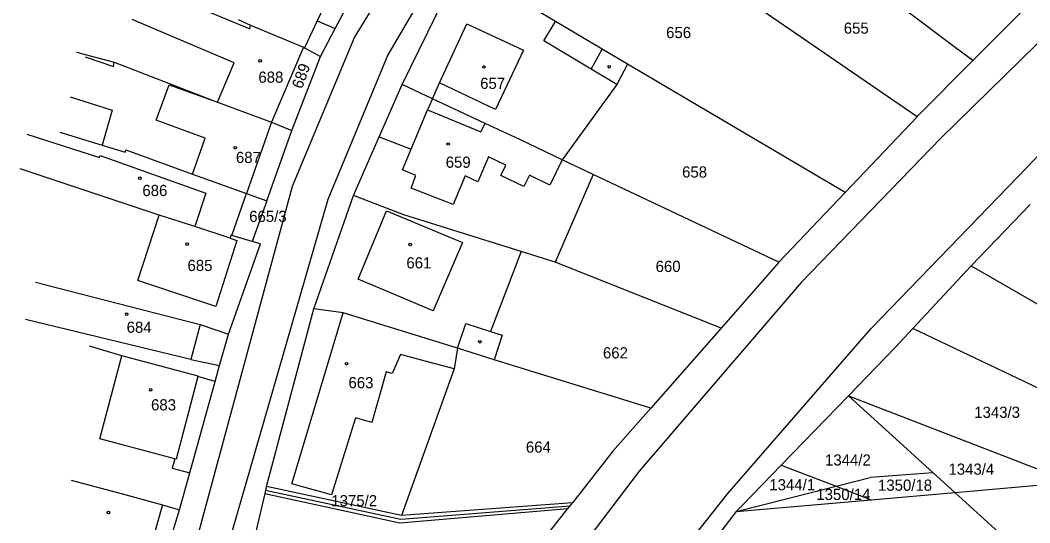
# Model space of a CAD drawing. Extents: x -563148 to -561712, y -1182311 to -1179502.
# Drawn here: x -562823.3 to -562687.9, y -1181313.6 to -1181246.2 of the extents above; entities that cross this region are included whole.
import ezdxf

# ---------------------------------------------------------------- set-up
doc = ezdxf.new("R2010")
doc.units = 0
for name, color, linetype in [('Vrstva 55', 7, 'Continuous'), ('Vrstva 56', 7, 'Continuous'), ('Vrstva 57', 7, 'Continuous')]:
    doc.layers.add(name, color=color, linetype=linetype)

msp = doc.modelspace()

# ---------------------------------------------------------------- linework, layer by layer
at = {"layer": 'Vrstva 55'}
for p, q in [((-562772.07, -1181254.85), (-562764.25, -1181238.82)), ((-562751.51, -1181246.42), (-562764.25, -1181238.82)), ((-562695.59, -1181251.65), (-562682.72, -1181238.72)), ((-562703.06, -1181259.17), (-562728.04, -1181242.02)), ((-562781.04, -1181247.33), (-562779.24, -1181243.92)), ((-562697.78, -1181250.01), (-562704.76, -1181244.75)), ((-562794.05, -1181246.16), (-562792.4, -1181246.88)), ((-562792.4, -1181246.88), (-562785.29, -1181249.87)), ((-562783.04, -1181251.1), (-562781.04, -1181247.33)), ((-562745.28, -1181250.13), (-562751.51, -1181246.42)), ((-562785.29, -1181249.87), (-562789.59, -1181259.92)), ((-562785.29, -1181249.87), (-562785.19, -1181249.96)), ((-562785.19, -1181249.96), (-562783.04, -1181251.1)), ((-562741.87, -1181252.15), (-562745.28, -1181250.13)), ((-562695.59, -1181251.65), (-562697.78, -1181250.01)), ((-562814.57, -1181251.14), (-562810.77, -1181252.43)), ((-562786.85, -1181261.03), (-562783.04, -1181251.1)), ((-562810.77, -1181252.43), (-562810.69, -1181251.87)), ((-562810.69, -1181251.87), (-562796.85, -1181257.21)), ((-562741.87, -1181252.15), (-562743.28, -1181254.87)), ((-562712.67, -1181269.31), (-562741.87, -1181252.15)), ((-562702.89, -1181258.99), (-562695.59, -1181251.65)), ((-562775.14, -1181261.85), (-562772.07, -1181254.85)), ((-562768.02, -1181256.76), (-562772.07, -1181254.85)), ((-562743.28, -1181254.87), (-562750.65, -1181264.94)), ((-562760.93, -1181260.09), (-562768.02, -1181256.76)), ((-562796.85, -1181257.21), (-562789.59, -1181259.92)), ((-562712.67, -1181269.31), (-562703.06, -1181259.17)), ((-562703.06, -1181259.17), (-562702.89, -1181258.99)), ((-562790.23, -1181270.46), (-562786.85, -1181261.03)), ((-562789.59, -1181259.92), (-562786.85, -1181261.03)), ((-562756.3, -1181262.23), (-562760.93, -1181260.09)), ((-562817.95, -1181261.26), (-562812.31, -1181262.99)), ((-562778.6, -1181269.72), (-562775.14, -1181261.85)), ((-562750.65, -1181264.94), (-562756.3, -1181262.23)), ((-562812.31, -1181262.99), (-562809.23, -1181263.94)), ((-562809.23, -1181263.94), (-562809.11, -1181263.61)), ((-562809.11, -1181263.61), (-562800.2, -1181266.89)), ((-562746.48, -1181266.91), (-562750.65, -1181264.94)), ((-562804.67, -1181272.35), (-562823.28, -1181266.16)), ((-562800.2, -1181266.89), (-562792.94, -1181269.48)), ((-562746.48, -1181266.91), (-562751.55, -1181278.69)), ((-562721.58, -1181278.68), (-562746.48, -1181266.91)), ((-562794.91, -1181275.09), (-562792.94, -1181269.48)), ((-562792.94, -1181269.48), (-562790.23, -1181270.46)), ((-562790.23, -1181270.46), (-562792.18, -1181275.9)), ((-562783.92, -1181284.92), (-562778.6, -1181269.72)), ((-562771.87, -1181272.31), (-562778.6, -1181269.72)), ((-562721.58, -1181278.68), (-562712.67, -1181269.31)), ((-562687.87, -1181270.93), (-562695.79, -1181279.15)), ((-562799.86, -1181273.88), (-562804.67, -1181272.35)), ((-562759.56, -1181276.15), (-562771.87, -1181272.31)), ((-562795.13, -1181275.43), (-562799.86, -1181273.88)), ((-562795.05, -1181275.05), (-562795.13, -1181275.43)), ((-562794.91, -1181275.09), (-562795.05, -1181275.05)), ((-562792.18, -1181275.9), (-562794.91, -1181275.09)), ((-562791.06, -1181276.23), (-562792.18, -1181275.9)), ((-562795.37, -1181288.31), (-562791.06, -1181276.23)), ((-562756.11, -1181277.24), (-562760.23, -1181287.98)), ((-562756.11, -1181277.24), (-562759.56, -1181276.15)), ((-562751.55, -1181278.69), (-562756.11, -1181277.24)), ((-562729.32, -1181287.5), (-562751.55, -1181278.69)), ((-562721.8, -1181278.93), (-562729.32, -1181287.5)), ((-562721.58, -1181278.68), (-562721.8, -1181278.93)), ((-562695.79, -1181279.15), (-562703.62, -1181287.57)), ((-562695.79, -1181279.15), (-562654.44, -1181303.1)), ((-562821.24, -1181281.33), (-562799.16, -1181287.04)), ((-562790.26, -1181308.73), (-562783.92, -1181284.92)), ((-562779.97, -1181285.44), (-562783.92, -1181284.92)), ((-562764.66, -1181290.2), (-562779.97, -1181285.44)), ((-562799.16, -1181287.04), (-562795.37, -1181288.31)), ((-562760.23, -1181287.98), (-562758.68, -1181288.47)), ((-562729.32, -1181287.5), (-562738.75, -1181298.24)), ((-562703.62, -1181287.57), (-562705.97, -1181290.09)), ((-562663.74, -1181306.52), (-562703.62, -1181287.57)), ((-562796.55, -1181292.52), (-562795.37, -1181288.31)), ((-562758.68, -1181288.47), (-562759.74, -1181291.78)), ((-562809.66, -1181291.24), (-562814.01, -1181289.91)), ((-562764.66, -1181290.2), (-562765.11, -1181292.98)), ((-562759.74, -1181291.78), (-562764.66, -1181290.2)), ((-562712.25, -1181296.57), (-562705.97, -1181290.09)), ((-562806.12, -1181292.17), (-562809.66, -1181291.24)), ((-562799.43, -1181293.94), (-562806.12, -1181292.17)), ((-562738.75, -1181298.24), (-562759.74, -1181291.78)), ((-562797.16, -1181294.67), (-562796.55, -1181292.52)), ((-562765.11, -1181292.98), (-562772.17, -1181312.61)), ((-562800.55, -1181306.89), (-562797.16, -1181294.67)), ((-562799.45, -1181294.01), (-562799.43, -1181293.94)), ((-562797.16, -1181294.67), (-562799.45, -1181294.01)), ((-562721.28, -1181305.89), (-562712.25, -1181296.57)), ((-562712.25, -1181296.57), (-562682.3, -1181308.15)), ((-562700.89, -1181306.91), (-562712.25, -1181296.57)), ((-562738.75, -1181298.24), (-562743.82, -1181304.01)), ((-562743.82, -1181304.01), (-562749.23, -1181310.92)), ((-562801.94, -1181311.87), (-562800.55, -1181306.89)), ((-562726.43, -1181311.21), (-562721.28, -1181305.89)), ((-562721.28, -1181305.89), (-562713.92, -1181308.71)), ((-562700.89, -1181306.91), (-562709.36, -1181307.55)), ((-562700.89, -1181306.91), (-562698, -1181309.53)), ((-562816.43, -1181307.88), (-562809.27, -1181309.79)), ((-562713.92, -1181308.71), (-562709.36, -1181307.55)), ((-562698, -1181309.53), (-562682.3, -1181308.15)), ((-562790.49, -1181309.69), (-562792.7, -1181319.03)), ((-562790.38, -1181309.22), (-562790.49, -1181309.69)), ((-562790.49, -1181309.69), (-562772.38, -1181313.59)), ((-562790.26, -1181308.73), (-562790.38, -1181309.22)), ((-562772.17, -1181312.61), (-562790.26, -1181308.73)), ((-562727.3, -1181312.1), (-562713.92, -1181308.71)), ((-562713.92, -1181308.71), (-562709.2, -1181310.51)), ((-562709.2, -1181310.51), (-562698, -1181309.53)), ((-562698, -1181309.53), (-562680.08, -1181325.78)), ((-562809.27, -1181309.79), (-562804.22, -1181311.21)), ((-562749.23, -1181310.92), (-562772.17, -1181312.61)), ((-562749.54, -1181311.32), (-562749.23, -1181310.92)), ((-562727.3, -1181312.1), (-562709.2, -1181310.51)), ((-562805.71, -1181324.25), (-562801.94, -1181311.87)), ((-562804.22, -1181311.21), (-562801.94, -1181311.87)), ((-562772.38, -1181313.59), (-562749.85, -1181311.7)), ((-562760.32, -1181324.88), (-562749.85, -1181311.7)), ((-562749.85, -1181311.7), (-562749.54, -1181311.32)), ((-562727.3, -1181312.1), (-562745.09, -1181335.08)), ((-562727.3, -1181312.1), (-562726.43, -1181311.21))]:
    msp.add_line(p, q, dxfattribs=at)
at = {"layer": 'Vrstva 56'}
for p, q in [((-562699.87, -1181262.05), (-562644.07, -1181207.39)), ((-562778.46, -1181248.57), (-562766.32, -1181228.74)), ((-562762.45, -1181231.13), (-562773.98, -1181250.88)), ((-562804.62, -1181242.35), (-562792.5, -1181247.41)), ((-562781.71, -1181242.64), (-562783.46, -1181246.31)), ((-562794.58, -1181251.94), (-562808.27, -1181246.12)), ((-562792.5, -1181247.41), (-562792.4, -1181246.88)), ((-562783.46, -1181246.31), (-562785.19, -1181249.96)), ((-562783.46, -1181246.31), (-562781.04, -1181247.33)), ((-562767.07, -1181254.62), (-562763.39, -1181246.73)), ((-562763.39, -1181246.73), (-562755.82, -1181250.24)), ((-562753.07, -1181249.02), (-562751.51, -1181246.42)), ((-562670.54, -1181246.93), (-562688.23, -1181265.89)), ((-562786.77, -1181268.49), (-562778.46, -1181248.57)), ((-562746.75, -1181252.8), (-562753.07, -1181249.02)), ((-562746.75, -1181252.8), (-562745.28, -1181250.13)), ((-562815.72, -1181250.53), (-562810.69, -1181251.87)), ((-562773.98, -1181250.88), (-562782.05, -1181270.27)), ((-562755.82, -1181250.24), (-562759.57, -1181258.19)), ((-562796.85, -1181257.21), (-562794.58, -1181251.94)), ((-562743.28, -1181254.87), (-562746.75, -1181252.8)), ((-562805.04, -1181259.65), (-562803.29, -1181254.88)), ((-562803.29, -1181254.88), (-562796.85, -1181257.21)), ((-562768.02, -1181256.76), (-562767.07, -1181254.62)), ((-562759.57, -1181258.19), (-562767.07, -1181254.62)), ((-562816.6, -1181256.5), (-562810.93, -1181258.3)), ((-562768.02, -1181256.76), (-562768.68, -1181258.25)), ((-562810.93, -1181258.3), (-562812.31, -1181262.99)), ((-562770.87, -1181263.54), (-562768.68, -1181258.25)), ((-562768.68, -1181258.25), (-562761.51, -1181261.2)), ((-562798.49, -1181262.05), (-562805.04, -1181259.65)), ((-562789.59, -1181259.92), (-562792.94, -1181269.48)), ((-562761.51, -1181261.2), (-562760.93, -1181260.09)), ((-562822.39, -1181261.52), (-562812.67, -1181264.63)), ((-562800.2, -1181266.89), (-562798.49, -1181262.05)), ((-562775.14, -1181261.85), (-562770.87, -1181263.54)), ((-562718.57, -1181281.38), (-562699.87, -1181262.05)), ((-562772.01, -1181266.27), (-562770.87, -1181263.54)), ((-562812.67, -1181264.63), (-562812.58, -1181264.38)), ((-562812.58, -1181264.38), (-562798.38, -1181269.4)), ((-562760.52, -1181264.56), (-562761.95, -1181267.89)), ((-562758.17, -1181265.66), (-562760.52, -1181264.56)), ((-562750.65, -1181264.94), (-562752.3, -1181268.35)), ((-562770.26, -1181267.06), (-562772.01, -1181266.27)), ((-562758.87, -1181267.06), (-562758.17, -1181265.66)), ((-562688.23, -1181265.89), (-562709.24, -1181287.61)), ((-562770.87, -1181268.76), (-562770.26, -1181267.06)), ((-562763.64, -1181267.11), (-562765.22, -1181270.96)), ((-562761.95, -1181267.89), (-562763.64, -1181267.11)), ((-562755.76, -1181268.54), (-562758.87, -1181267.06)), ((-562755.01, -1181267.02), (-562755.76, -1181268.54)), ((-562752.3, -1181268.35), (-562755.01, -1181267.02)), ((-562803.26, -1181329.28), (-562786.77, -1181268.49)), ((-562765.22, -1181270.96), (-562770.87, -1181268.76)), ((-562798.38, -1181269.4), (-562799.86, -1181273.88)), ((-562782.05, -1181270.27), (-562799.33, -1181330.15)), ((-562777.98, -1181280.94), (-562774.19, -1181271.77)), ((-562774.19, -1181271.77), (-562764, -1181276.03)), ((-562807.53, -1181281.12), (-562804.67, -1181272.35)), ((-562794.23, -1181275.77), (-562797.07, -1181284.63)), ((-562795.13, -1181275.43), (-562794.23, -1181275.77)), ((-562764, -1181276.03), (-562767.94, -1181285.2)), ((-562797.07, -1181284.63), (-562807.53, -1181281.12)), ((-562767.94, -1181285.2), (-562777.98, -1181280.94)), ((-562718.57, -1181281.38), (-562740.32, -1181306.67)), ((-562800.42, -1181291.73), (-562822.58, -1181286.36)), ((-562786.85, -1181308.4), (-562779.97, -1181285.44)), ((-562799.16, -1181287.04), (-562800.42, -1181291.73)), ((-562764.66, -1181290.2), (-562763.56, -1181286.91)), ((-562763.56, -1181286.91), (-562760.23, -1181287.98)), ((-562728.42, -1181309.69), (-562709.24, -1181287.61)), ((-562812.59, -1181302.34), (-562809.66, -1181291.24)), ((-562800.42, -1181291.73), (-562796.55, -1181292.52)), ((-562772.28, -1181291.03), (-562773.4, -1181293.58)), ((-562769.01, -1181291.92), (-562772.28, -1181291.03)), ((-562765.11, -1181292.98), (-562769.01, -1181291.92)), ((-562774.24, -1181293.37), (-562776.12, -1181300.16)), ((-562773.4, -1181293.58), (-562774.24, -1181293.37)), ((-562799.45, -1181294.01), (-562802.36, -1181305.06)), ((-562778.32, -1181299.55), (-562781.56, -1181309.87)), ((-562776.12, -1181300.16), (-562778.32, -1181299.55)), ((-562802.55, -1181305.01), (-562812.59, -1181302.34)), ((-562802.55, -1181305.01), (-562802.89, -1181306.29)), ((-562802.36, -1181305.06), (-562802.55, -1181305.01)), ((-562802.89, -1181306.29), (-562800.55, -1181306.89)), ((-562740.32, -1181306.67), (-562756.42, -1181327.84)), ((-562781.56, -1181309.87), (-562786.85, -1181308.4)), ((-562790.38, -1181309.22), (-562772.27, -1181313.1)), ((-562747.24, -1181333.44), (-562728.42, -1181309.69)), ((-562804.22, -1181311.21), (-562806.51, -1181319.32)), ((-562772.27, -1181313.1), (-562749.54, -1181311.32))]:
    msp.add_line(p, q, dxfattribs=at)
at = {"layer": 'Vrstva 57'}
for centre in [(-562791.11, -1181251.68), (-562761.11, -1181252.5), (-562744.31, -1181252.47), (-562794.45, -1181263.33), (-562765.92, -1181262.83), (-562807.26, -1181267.42), (-562800.88, -1181276.25), (-562771.01, -1181276.29), (-562809.01, -1181285.63), (-562761.66, -1181289.33), (-562779.52, -1181292.28), (-562805.79, -1181295.77), (-562811.46, -1181312.22)]:
    msp.add_circle(centre, 0.175, dxfattribs=at)

# ---------------------------------------------------------------- texts
for s, p in [('656', (-562736.69, -1181248.64)), ('655', (-562712.88, -1181248.05)), ('688', (-562791.35, -1181254.62)), ('657', (-562761.62, -1181255.45)), ('687', (-562794.36, -1181265.38)), ('659', (-562766.24, -1181266.02)), ('658', (-562734.55, -1181267.33)), ('686', (-562806.9, -1181269.81)), ('665/3', (-562792.58, -1181273.28)), ('685', (-562800.85, -1181279.86)), ('661', (-562771.51, -1181279.51)), ('660', (-562738.1, -1181279.98)), ('684', (-562809.01, -1181288.14)), ('662', (-562745.16, -1181291.57)), ('663', (-562779.27, -1181295.57)), ('683', (-562805.74, -1181298.54)), ('1343/3', (-562695.39, -1181299.54)), ('664', (-562755.49, -1181304.2)), ('1344/2', (-562715.39, -1181305.93)), ('1343/4', (-562698.84, -1181307.16)), ('1344/1', (-562722.86, -1181309.25)), ('1350/18', (-562708.29, -1181309.31)), ('1350/14', (-562716.56, -1181310.55)), ('1375/2', (-562781.57, -1181311.39))]:
    msp.add_text(s, height=1.5, dxfattribs=at).set_placement(p)
msp.add_text('689', height=1.5, rotation=70.3206, dxfattribs=at).set_placement((-562785.5, -1181255.53))

doc.saveas('drawing.dxf')
